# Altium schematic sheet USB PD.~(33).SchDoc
size A3; SheetNumber: 5; SheetTotal: 5
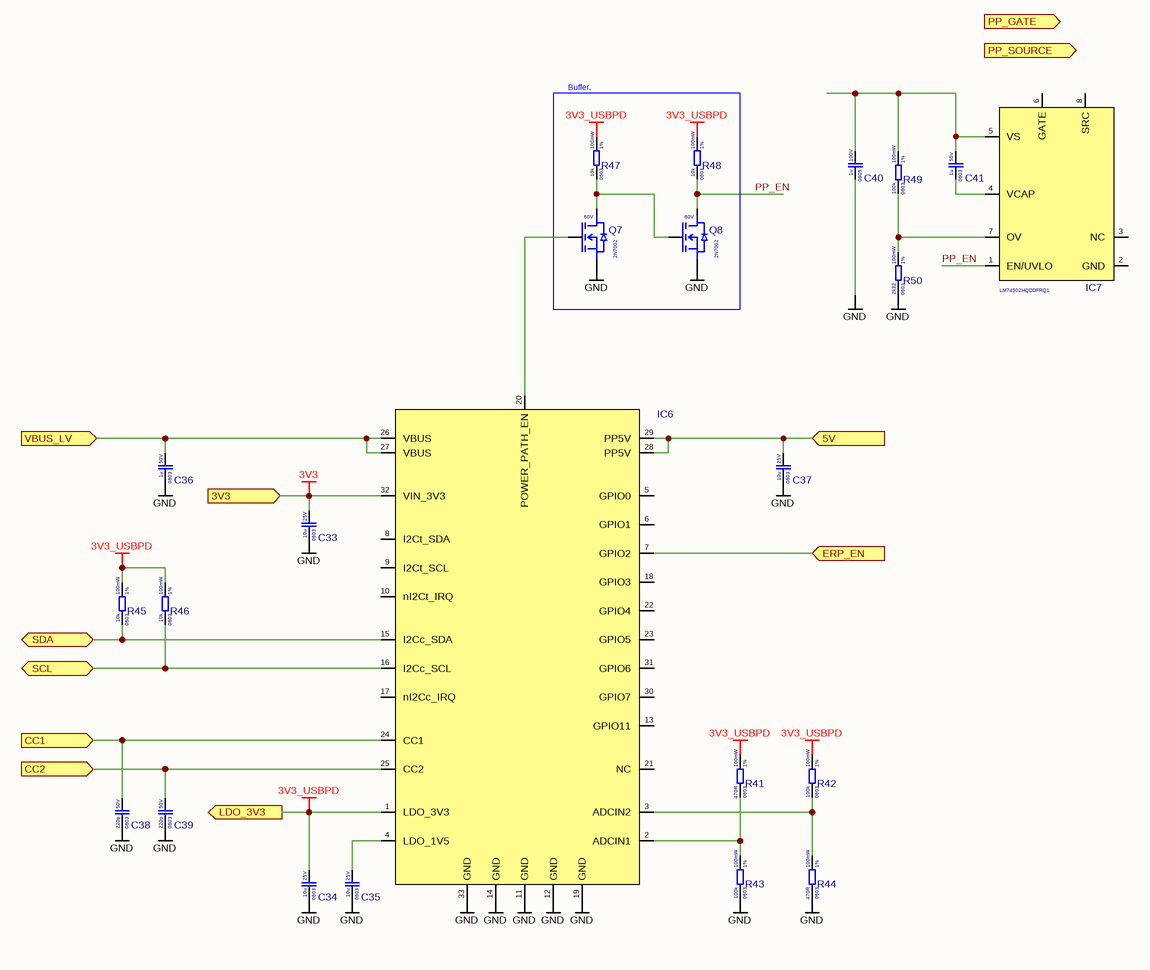
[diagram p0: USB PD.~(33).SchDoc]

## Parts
C33  Voltage Rating: 25V  Case Code (Imperial): 0603  Capacitance: 10u  [CAP 0603]  (hidden comment: CL10A106MA8NRNC)
C34  Voltage Rating: 25V  Case Code (Imperial): 0603  Capacitance: 10u  [CAP 0603]  (hidden comment: CL10A106MA8NRNC)
C35  Voltage Rating: 25V  Case Code (Imperial): 0603  Capacitance: 10u  [CAP 0603]  (hidden comment: CL10A106MA8NRNC)
C36  Voltage Rating: 50V  Case Code (Imperial): 0603  Capacitance: 1u  [CAP 0603]  (hidden comment: CL10A105KB8NNNC)
C37  Voltage Rating: 25V  Case Code (Imperial): 0603  Capacitance: 10u  [CAP 0603]  (hidden comment: CL10A106MA8NRNC)
C38  Voltage Rating: 50V  Case Code (Imperial): 0603  Capacitance: 220p  [CAP 0603]  (hidden comment: CL10B221KB8NNNC)
C39  Voltage Rating: 50V  Case Code (Imperial): 0603  Capacitance: 220p  [CAP 0603]  (hidden comment: CL10B221KB8NNNC)
C40  Voltage Rating: 100V  Case Code (Imperial): 0805  Capacitance: 1u  [Cap_0805]  (hidden comment: CC0805KKX7R0BB105)
C41  Voltage Rating: 50V  Case Code (Imperial): 0603  Capacitance: 1u  [CAP 0603]  (hidden comment: CL10A105KB8NNNC)
IC6  TPS26750SRSMR  [VQFN (32) 4x4]  (value not drawn)
IC7  LM74502HQDDFRQ1  [SOT-23-8]
Q7  Voltage: 60V  [SOT-23 GSD]  (hidden comment: 2N7002)
Q8  Voltage: 60V  [SOT-23 GSD]  (hidden comment: 2N7002)
R41  Resistance Tolerance: 1%  Resistance: 470R  Power Rating: 100mW  Case Code (Imperial): 0603  [RES_0603]  (hidden comment: 0603WAF4700T5E)
R42  Resistance Tolerance: 1%  Resistance: 100k  Power Rating: 100mW  Case Code (Imperial): 0603  [RES_0603]  (hidden comment: 0603WAF1003T5E)
R43  Resistance Tolerance: 1%  Resistance: 100k  Power Rating: 100mW  Case Code (Imperial): 0603  [RES_0603]  (hidden comment: 0603WAF1003T5E)
R44  Resistance Tolerance: 1%  Resistance: 470R  Power Rating: 100mW  Case Code (Imperial): 0603  [RES_0603]  (hidden comment: 0603WAF4700T5E)
R45  Resistance Tolerance: 1%  Resistance: 10k  Power Rating: 100mW  Case Code (Imperial): 0603  [RES_0603]  (hidden comment: 0603WAF1002T5E)
R46  Resistance Tolerance: 1%  Resistance: 10k  Power Rating: 100mW  Case Code (Imperial): 0603  [RES_0603]  (hidden comment: 0603WAF1002T5E)
R47  Resistance Tolerance: 1%  Resistance: 10k  Power Rating: 100mW  Case Code (Imperial): 0603  [RES_0603]  (hidden comment: 0603WAF1002T5E)
R48  Resistance Tolerance: 1%  Resistance: 10k  Power Rating: 100mW  Case Code (Imperial): 0603  [RES_0603]  (hidden comment: 0603WAF1002T5E)
R49  Resistance Tolerance: 1%  Resistance: 100k  Power Rating: 100mW  Case Code (Imperial): 0603  [RES_0603]  (hidden comment: 0603WAF1003T5E)
R50  Resistance Tolerance: 1%  Resistance: 2k32  Power Rating: 100mW  Case Code (Imperial): 0603  [RES_0603]  (hidden comment: FRC0603F2321TS)

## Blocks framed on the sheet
Buffer.: Q7 Q8 R47 R48

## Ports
3V3 (in, see Arhitecture[4B], Power distribution[5D]), 5V (in, see Arhitecture[4B], Power distribution[5C]), CC1 (in, see Arhitecture[3B]), CC2 (in, see Arhitecture[3B]), ERP_EN (in, see Arhitecture[3B]), LDO_3V3 (out, see Arhitecture[3B]), PP_GATE (out, see Arhitecture[4B]), PP_SOURCE (out, see Arhitecture[4B]), SCL (bidir, see Arhitecture[4B], Charger[3C]), SDA (bidir, see Arhitecture[4B], Charger[3C]), VBUS_LV (in, see Arhitecture[3B])

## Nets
3V3: C33.2 IC6.32(VIN_3V3) ; port 3V3
3V3_USBPD: C34.2 IC6.1(LDO_3V3) R41.2 R42.2 R45.2 R46.2 R47.2 R48.2 ; port LDO_3V3
GND: C33.1 C34.1 C35.1 C36.1 C37.1 C38.1 C39.1 C40.1 IC6.11(GND) IC6.12(GND) IC6.14(GND) IC6.19(GND) IC6.33(GND) Q7.S Q8.S R43.1 R44.1 R50.1
5V: C37.2 IC6.28(PP5V) IC6.29(PP5V) ; port 5V
CC1: C38.2 IC6.24(CC1) ; port CC1
CC2: C39.2 IC6.25(CC2) ; port CC2
ERP_EN: IC6.7(GPIO2) ; port ERP_EN
PP_EN: IC7.1(EN/UVLO) Q8.D R48.1
SCL: IC6.16(I2Cc_SCL) R46.1 ; port SCL
SDA: IC6.15(I2Cc_SDA) R45.1 ; port SDA
VBUS_LV: C36.2 IC6.26(VBUS) IC6.27(VBUS) ; port VBUS_LV
NetC35_2: C35.2 IC6.4(LDO_1V5)
NetC40_2: C40.2 C41.2 IC7.5(VS) R49.2
NetC41_1: C41.1 IC7.4(VCAP)
NetIC6_2: IC6.2(ADCIN1) R41.1 R43.2
NetIC6_3: IC6.3(ADCIN2) R42.1 R44.2
NetIC6_20: IC6.20(POWER_PATH_EN) Q7.G
NetIC7_7: IC7.7(OV) R49.1 R50.2
NetQ7_D: Q7.D Q8.G R47.1

Not connected (* = marked no-connect by the designer): IC6 5(GPIO0) 6(GPIO1) 8(I2Ct_SDA) 9(I2Ct_SCL) 10(nI2Ct_IRQ) 13(GPIO11) 17(nI2Cc_IRQ) 18(GPIO3) 21(NC) 22(GPIO4) 23(GPIO5) 30(GPIO7) 31(GPIO6); IC7 2(GND) 3(NC) 6(GATE) 8(SRC)

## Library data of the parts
C33-C35 C37 = CL10A106MA8NRNC: Cap 10uF 25V 0603 X5R; Manufacturer: Samsung
C36 C41 = CL10A105KB8NNNC: Cap 1uF 50V 0603 X5R; Manufacturer: Samsung
C38 C39 = CL10B221KB8NNNC: Cap 220pF 50V 0603 X7R; Manufacturer: Samsung
C40 = CC0805KKX7R0BB105: Cap 1uF 100V 0805 X7R; Manufacturer: Yageo
IC6 = TPS26750SRSMR: USB PD IC EPR 240W; Manufacturer: Texas Instruments
IC7 = LM74502HQDDFRQ1: High-side switch controller IC 3.2~65V Reverse polarity protection; Manufacturer: Texas Instruments
Q7 Q8 = 2N7002: nMOS 60V 115mA SOT-23; Manufacturer: Jiangsu Changjing Electronics Technology Co., Ltd.
R41 R44 = 0603WAF4700T5E: Res 470R 0603 1% 100mW 75V; Manufacturer: Uni-Royal
R42 R43 R49 = 0603WAF1003T5E: Res 100k 0603 1% 100mW 75V; Manufacturer: Uni-Royal
R45-R48 = 0603WAF1002T5E: Res 10k 0603 1% 100mW 75V; Manufacturer: Uni-Royal
R50 = FRC0603F2321TS: Res 2k32 0603 1% 100mW 75V; Manufacturer: Uni-Royal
